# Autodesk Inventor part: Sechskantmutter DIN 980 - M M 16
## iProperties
Shininess: 64.0
Length Units: 11269
Angle Units: 11279
Time Units: 11290
Mass Units: 11283
Length Display Precision: 3
Angle Display Precision: 2
Compacted: True
Part Number: Sechskantmutter DIN 980 - M M 16
Document SubType Name: Standard Catalog Part
Created: 2004-12
Material: Standard
Description: Sechskantmutter, mit Klemmteil, Ganzmetallmutter
Vendor: NORM8
Designer: L.Vaida
Manufacturer: Standard
Standards Organization: Custom
Density: 0.0
Volumn: 0.0
Area: 0.0
PropertySet Name: Model Information
Control State: 0
Master: False
Checked Out: False
CNS_NB: Sechskantmutter DIN 980 - M M 16
CNS_NN: DIN 980
CNS_NT: Sechskantmutter, mit Klemmteil, Ganzmetallmutter
CNS_NBSYN: Sechskantmutter DIN 980 - M $NENN.
CNS_LINA: Sechskantmutter DIN 980 - M M 16
CNS_NENN: M 16
CNS_D: 16.000
CNS_D1: 13.835
CNS_P: 2.000
CNS_M: 16.000
CNS_S: 24.000
CNS_KT: X
PSOL_IDENT_0: {E:\CAD-Programme\cadenas\partsolutions\data\23d-libs\norm\din_en_iso\muttern\muttern_mit_klemmteil\
PSOL_IDENT_1: din_980.prj},167 {M=Nenngewinde},{VTYP=3D},{NB=Sechskantmutter DIN 980 - M M 16},{NN=DIN 980},{DATE=
PSOL_IDENT_2: 29.1.2004},{GEOMDATE=26.11.2003},{VERSION=v1},{LINEID=100},{LINESUBID=-1},{WBVAR=}  {NB=Sechskantmut
PSOL_IDENT_3: ter DIN 980 - M M 16},{LINA=Sechskantmutter DIN 980 - M M 16},{KT=X},{IDNR=},{NENN=M 16},{D=16.000},
PSOL_IDENT_4: {D1=13.835},{P=2.000},{M=16.000},{S=24.000}
Title: Sechskantmutter DIN 980 - M M 16
Author: L.Vaida
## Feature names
1. Drehung1 [Revolution]
2. Extrusion1
